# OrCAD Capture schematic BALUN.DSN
size A
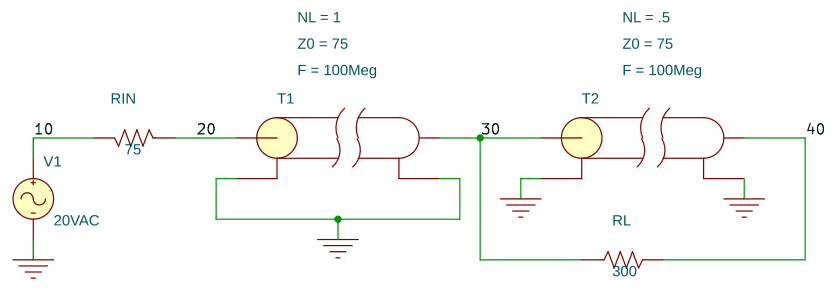
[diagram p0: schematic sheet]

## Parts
RIN  75  [AX/RC05]
RL  300  [AX/RC05]
T1  T
T2  T
V1  VAC

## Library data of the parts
RIN RL = R
T1 = T: F: 100Meg; NL: 1; Z0: 75
T2 = T: F: 100Meg; NL: .5; Z0: 75
V1 = VAC: ACMAG: 20VAC

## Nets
0: T1.2(A-) T1.4(B-) T2.2(A-) T2.4(B-) V1.2(-)
10: RIN.2 V1.1(+)
20: RIN.1 T1.1(A+)
30: RL.1 T1.3(B+) T2.1(A+)
40: RL.2 T2.3(B+)
